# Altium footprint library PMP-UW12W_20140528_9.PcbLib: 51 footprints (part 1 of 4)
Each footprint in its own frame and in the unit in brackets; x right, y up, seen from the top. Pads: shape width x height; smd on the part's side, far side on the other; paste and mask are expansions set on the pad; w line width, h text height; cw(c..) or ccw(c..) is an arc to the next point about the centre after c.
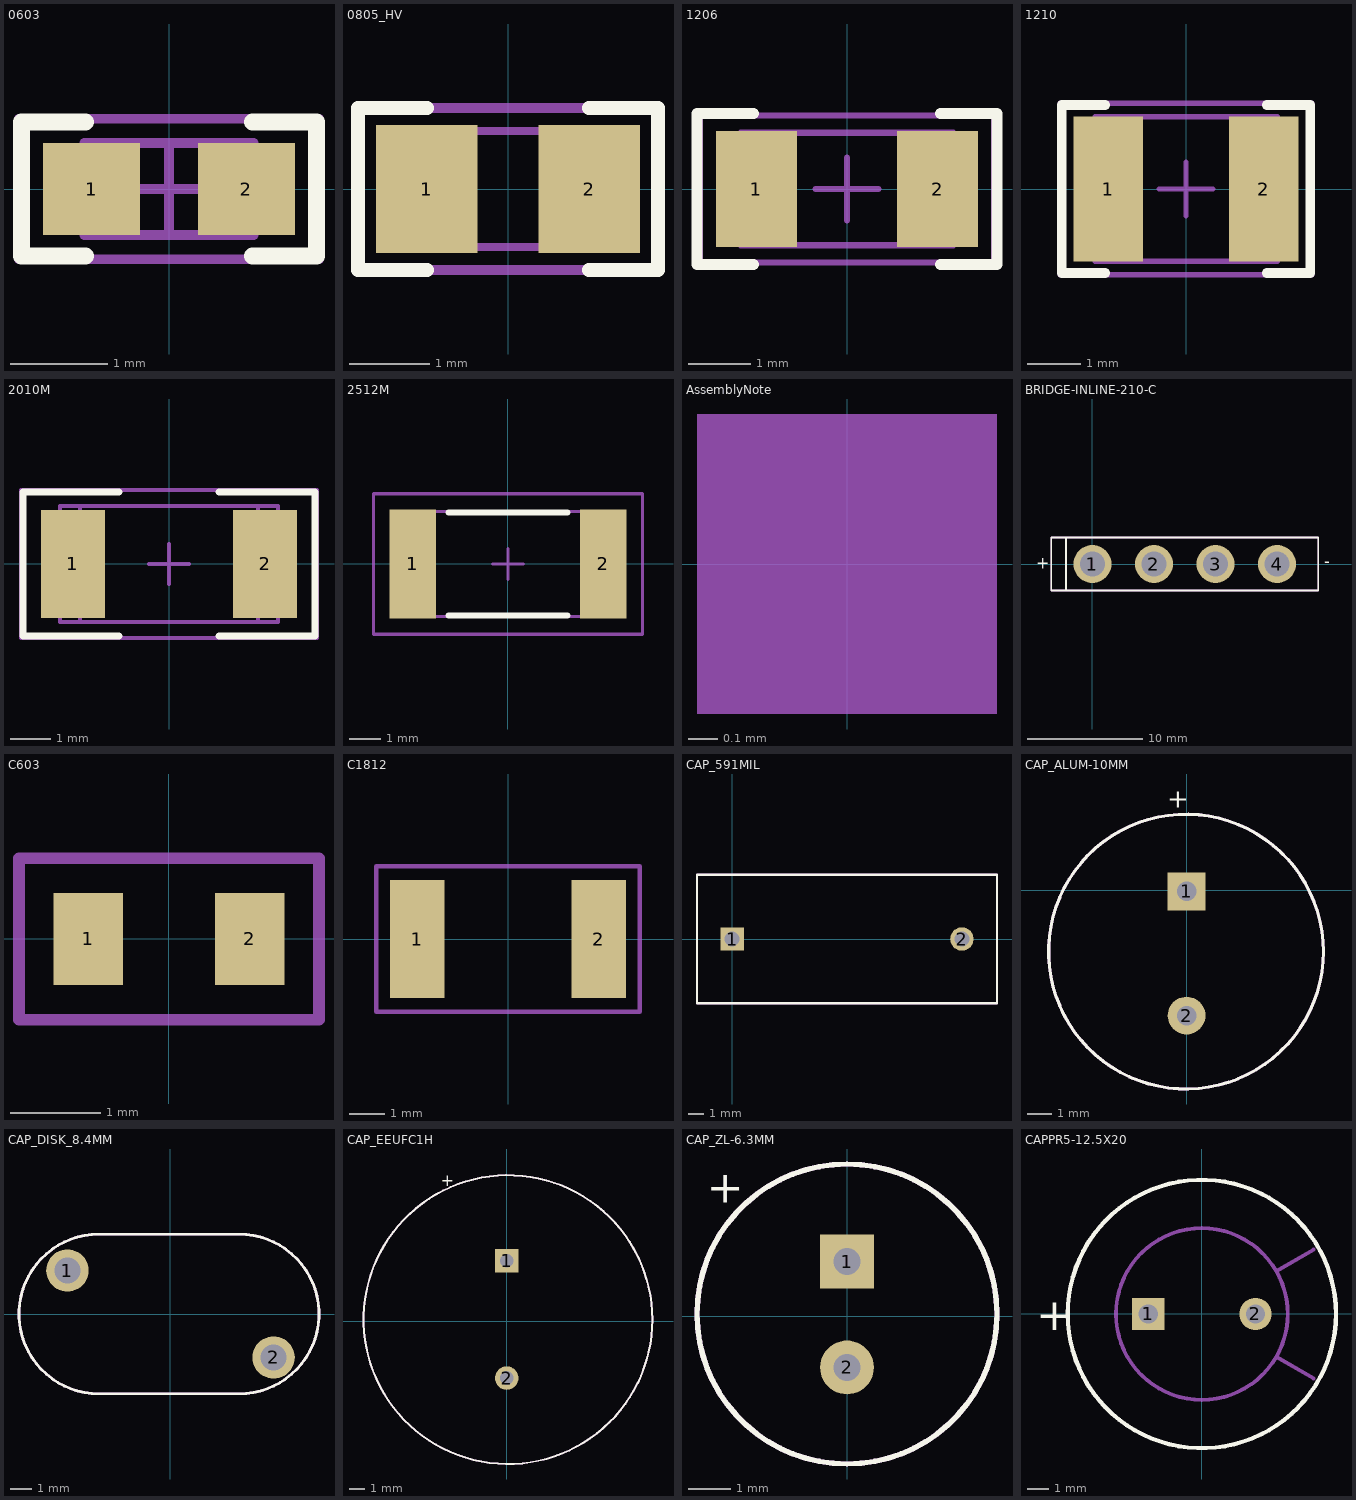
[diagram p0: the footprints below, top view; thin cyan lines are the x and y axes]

## 0603 [mm] "0603 from SM-752 data"
height 0.85
pads (2):
  rect 1x0.95 smd: 1(-0.8,0) 2(0.8,0)
Top Overlay:
  lines w0.178: -0.864,-0.691 -1.524,-0.691 -1.524,0.693 -0.864,0.693 ; 0.864,-0.691 1.524,-0.691 1.524,0.693 0.864,0.693
Mechanical 5:
  lines w0.1: -1.55,-0.725 -1.55,0.725 1.55,0.725 1.55,-0.725 -1.55,-0.725
  text ".Designator" at -0.864,1.067 h1.02
Mechanical 13:
  lines w0.1: -0.55,-0.475 -0.55,0.475 ; 0.55,-0.475 0.55,0.475 ; -0.875,-0.475 0.875,-0.475 0.875,0.475 -0.875,0.475 -0.875,-0.475
Mechanical 15:
  lines w0.1: -0.475,0 0.475,0 ; 0,-0.475 0,0.475 ; -1.55,-0.725 1.55,-0.725 1.55,0.725 -1.55,0.725 -1.55,-0.725
3D body: height 0.85, standoff 0, extent -0.874,-0.474 -0.551,0.474
3D body: height 0.85, standoff 0, extent -0.549,-0.474 0.549,0.474
3D body: height 0.85, standoff 0, extent 0.551,-0.474 0.874,0.474

## 0805_HV [mil] "0805 with 30mil clearance between pads"
height 43.31
pads (2):
  rect 50x63 smd: 1(-40,0) 2(40,0)
Top Overlay:
  lines w7: -40,-40 -74,-40 -74,0 -74,40 -40,40 ; 40,-40 74,-40 74,0 74,40 40,40
Mechanical 5:
  lines w5: -74,-40 74,-40 74,40 -74,40 -74,-40
  text ".Designator" at -64,-17 h35
Mechanical 13:
  lines w3.94: -25.59,-28.54 -25.59,28.54 ; 25.59,-28.54 25.59,28.54 ; -43.31,-28.54 -43.31,28.54 43.31,28.54 43.31,-28.54 -43.31,-28.54
3D body: height 43.31, standoff 0, extent 25.61,-28.52 43.29,28.52
3D body: height 43.31, standoff 0, extent -25.57,-28.52 25.57,28.52
3D body: height 43.31, standoff 0, extent -43.29,-28.52 -25.61,28.52

## 1206 [mm] "1206 from SM-752 data"
height 1.35
pads (2):
  rect 1.3x1.85 smd: 1(-1.45,0) 2(1.45,0)
Top Overlay:
  lines w0.178: -1.5,-1.21 -2.4,-1.21 -2.4,1.21 -1.5,1.21 ; 1.5,-1.21 2.4,-1.21 2.4,1.21 1.5,1.21
Mechanical 5:
  lines w0.1: -1.7,-0.9 -1.7,0.9 1.7,0.9 1.7,-0.9 -1.7,-0.9
  text ".Designator" at -1.475,-0.4 h0.81
Mechanical 13:
  lines w0.1: -1.2,-0.9 -1.2,0.9 ; 1.2,-0.9 1.2,0.9 ; -1.7,-0.9 -1.7,0.9 1.7,0.9 1.7,-0.9 -1.7,-0.9
Mechanical 15:
  lines w0.1: -0.5,0 0.5,0 ; 0,-0.5 0,0.5 ; -2.35,-1.175 -2.35,1.175 2.35,1.175 2.35,-1.175 -2.35,-1.175
3D body: height 1.35, standoff 0, extent 1.201,-0.899 1.699,0.899
3D body: height 1.35, standoff 0, extent -1.199,-0.899 1.199,0.899
3D body: height 1.35, standoff 0, extent -1.699,-0.899 -1.201,0.899

## 1210 [mm] "1210 from SM-752 data"
height 1.35
pads (2):
  rect 1.3x2.7 smd: 1(-1.45,0) 2(1.45,0)
Top Overlay:
  lines w0.178: -1.511,-1.568 -2.316,-1.568 -2.316,1.568 -1.511,1.568 ; 1.511,-1.568 2.316,-1.568 2.316,1.568 1.511,1.568
Mechanical 5:
  lines w0.1: -1.7,-1.35 -1.7,1.35 1.7,1.35 1.7,-1.35 -1.7,-1.35
  text ".Designator" at -1.905,-3.556 h1.52
Mechanical 13:
  lines w0.1: -1.2,-1.35 -1.2,1.35 ; 1.2,-1.35 1.2,1.35 ; -1.7,-1.35 1.7,-1.35 1.7,1.35 -1.7,1.35 -1.7,-1.35
Mechanical 15:
  lines w0.1: -0.5,0 0.5,0 ; 0,-0.5 0,0.5 ; -2.35,-1.6 2.35,-1.6 2.35,1.6 -2.35,1.6 -2.35,-1.6
3D body: height 1.35, standoff 0, extent 1.201,-1.349 1.699,1.349
3D body: height 1.35, standoff 0, extent -1.199,-1.349 1.199,1.349
3D body: height 1.35, standoff 0, extent -1.699,-1.349 -1.201,1.349

## 2010M [mm]
height 0.71
pads (2):
  rect 1.6x2.7 smd: 1(-2.4,0) 2(2.4,0)
Top Overlay:
  lines w0.178: -1.25,-1.8 -3.65,-1.8 -3.65,1.8 -1.25,1.8 ; 1.25,-1.8 3.65,-1.8 3.65,1.8 1.25,1.8
Mechanical 5:
  lines w0.1: -2.73,-1.45 2.73,-1.45 2.73,1.45 -2.73,1.45 -2.73,-1.45
  text ".Designator" at -1.875,-0.5 h1.02
Mechanical 13:
  lines w0.1: -2.23,-1.45 -2.23,1.45 ; 2.23,-1.45 2.23,1.45 ; -2.73,-1.45 2.73,-1.45 2.73,1.45 -2.73,1.45 -2.73,-1.45
Mechanical 15:
  lines w0.1: -0.5,0 0.5,0 ; 0,-0.5 0,0.5 ; -3.7,-1.85 3.7,-1.85 3.7,1.85 -3.7,1.85 -3.7,-1.85
3D body: height 1.66, standoff 0, extent -2.729,-1.449 -2.231,1.449
3D body: height 1.66, standoff 0, extent -2.229,-1.449 2.229,1.449
3D body: height 1.66, standoff 0, extent 2.231,-1.449 2.729,1.449

## 2512M [mm] "Chip Resistor, Body 6.3x3.2mm, IPC Low Density"
height 0.71
pads (2):
  rect 1.5x3.5 smd: 1(-3.05,0) 2(3.05,0)
Top Overlay:
  lines w0.2: -1.9,-1.65 1.9,-1.65 ; -1.9,1.65 1.9,1.65
Mechanical 5:
  lines w0.1: -3.225,-1.675 -3.225,1.675 3.225,1.675 3.225,-1.675 -3.225,-1.675
  text ".Designator" at -1.85,-0.5 h1.02
Mechanical 13:
  lines w0.1: -2.463,-1.675 -2.463,1.675 ; 2.463,-1.675 2.463,1.675 ; -3.225,-1.675 -3.225,1.675 3.225,1.675 3.225,-1.675 -3.225,-1.675
Mechanical 15:
  lines w0.1: -0.5,0 0.5,0 ; 0,-0.5 0,0.5 ; -4.3,-2.25 -4.3,2.25 4.3,2.25 4.3,-2.25 -4.3,-2.25
3D body: height 0.71, standoff 0, extent 2.464,-1.674 3.224,1.674
3D body: height 0.71, standoff 0, extent -2.462,-1.674 2.462,1.674
3D body: height 0.71, standoff 0, extent -3.224,-1.674 -2.464,1.674

## AssemblyNote [mil] "Assembly Note"
Mechanical 5:
  rectangle: -20,-20 20,20
  text ".Comment" at 45,-20 h40
  text ".Designator" at -165,-20 h40

## BRIDGE-INLINE-210-C [mil]
pads (4):
  round 130 hole 86: 1(0,0) 2(210,0) 3(420,0) 4(630,0)
Top Overlay:
  lines w6: -90,-85 -90,90 ; -140,-90 770,-90 770,90 -140,90 -140,-90
  text "-" at 790.95,-9.8 h40
  text "+" at -192.35,-15.45 h40
Mechanical 5:
  lines w5: 770,-90 770,90
  lines w6: -90,-90 -90,90 ; 770,-90 -140,-90 -140,90 770,90
  text "+" at -192.35,-15.45 h30
  text "-" at 790.95,-9.8 h30
  text ".Designator" at 245,-35 h40

## C603 [mil]
pads (2):
  rect 30x40 smd mask+2: 1(-35,0) 2(35,0)
Mechanical 5:
  lines w5: -65,-35 65,-35 65,35 -65,35 -65,-35
  text ".Designator" at 265,30 h60

## C1812 [mil]
pads (2):
  rect 60x130 smd mask+2: 1(-100,0) 2(100,0)
Mechanical 5:
  lines w5: -145,-80 145,-80 145,80 -145,80 -145,-80
  text ".Designator" at -73,-20 h40

## CAP_591MIL [mil]
pads (2):
  rect 60x60 hole 38: 1(0,0)
  round 60 hole 38: 2(590,0)
Top Overlay:
  lines w6: -90,-165 -90,165 680,165 680,-165 -90,-165
Mechanical 5:
  lines w5: -90,-165 680,-165 680,165 -90,165 -90,-165
  text ".Designator" at 175,210 h60
Drill Drawing:
  lines w6: -90,-165 -90,165

## CAP_ALUM-10MM [mil]
pads (2):
  rect 60x60 hole 31: 1(0,-2)
  round 60 hole 31: 2(0,-199)
Top Overlay:
  circle w5: c-1,-97.5 r218
  text "+" at -30.47,130.46 h30
Mechanical 5:
  circle w5: c-1,-97.5 r218
  text "+" at -31.52,132.02 h30
  text ".Designator" at -290,110 h60

## CAP_DISK_8.4MM [mil]
pads (2):
  round 77 hole 47: 1(-187,79) 2(187.5,-79)
Top Overlay:
  lines w5: -130,-145 cw(c-130,0) -130,145 125,145 cw(c125,0) 125,-145 -130,-145
Mechanical 5:
  lines w5: -130,-145 cw(c-130,0) -130,145 125,145 cw(c125,0) 125,-145 -130,-145
  text ".Designator" at 90,-170 h60

## CAP_EEUFC1H [mil]
pads (2):
  rect 60x60 hole 35: 1(0.1,155)
  round 60 hole 35: 2(0,-145)
Top Overlay:
  circle w5: c3.4,4.6 r369.5
  text "+" at -133.85,372.79 h30
Mechanical 5:
  circle w5: c3.4,4.6 r369.5
  text "+" at -145,380 h30
  text ".Designator" at -385,350 h60

## CAP_ZL-6.3MM [mil]
pads (2):
  rect 50x50 hole 25: 1(0,50.5)
  round 50 hole 25: 2(0,-47.5)
Top Overlay:
  circle w5: c0,2 r139
  text "+" at -130,105 h30
Mechanical 5:
  circle w5: c0,2 r139
  text ".Designator" at 135,-55 h60
  text "+" at -130,105 h30

## CAPPR5-12.5X20 [mm] "Capacitor, Electrolytic, Radial; Body 12.5 x 20 mm (Dia.xH typ); Pin Spacing 5 mm (typ)"
height 22
pads (2):
  rect 1.5x1.5 hole 0.9: 1(-2.5,0)
  round 1.5 hole 0.9: 2(2.5,0)
Top Overlay:
  circle w0.2: c0,0 r6.25
  text "+" at -7.725,-0.75 h1.5
Mechanical 5:
  circle w0.127: c0,0 r6.25
  text ".Designator" at -1.524,-0.508 h1.02
  text "+" at -7.725,-0.75 h1.5
Mechanical 13:
  circle w0.178: c2.5,0 r0.3
  circle w0.178: c-2.5,0 r0.3
  circle w0.178: c0,0 r4
  lines w0.178: 3.464,-2 5.196,-3 ; 3.464,2 5.196,3
3D body: height 1, standoff -2.54, extent 2.195,-0.305 2.805,0.305
3D body: height 1, standoff -2.54, extent -2.805,-0.305 -2.195,0.305
3D body: height 22, standoff 0, extent 3.463,-3.001 6.01,3.001
3D body: height 22, standoff 0, extent -6.01,-6.01 5.197,6.01
3D body: height 22, standoff 0, extent -4.013,-4.013 5.197,4.013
